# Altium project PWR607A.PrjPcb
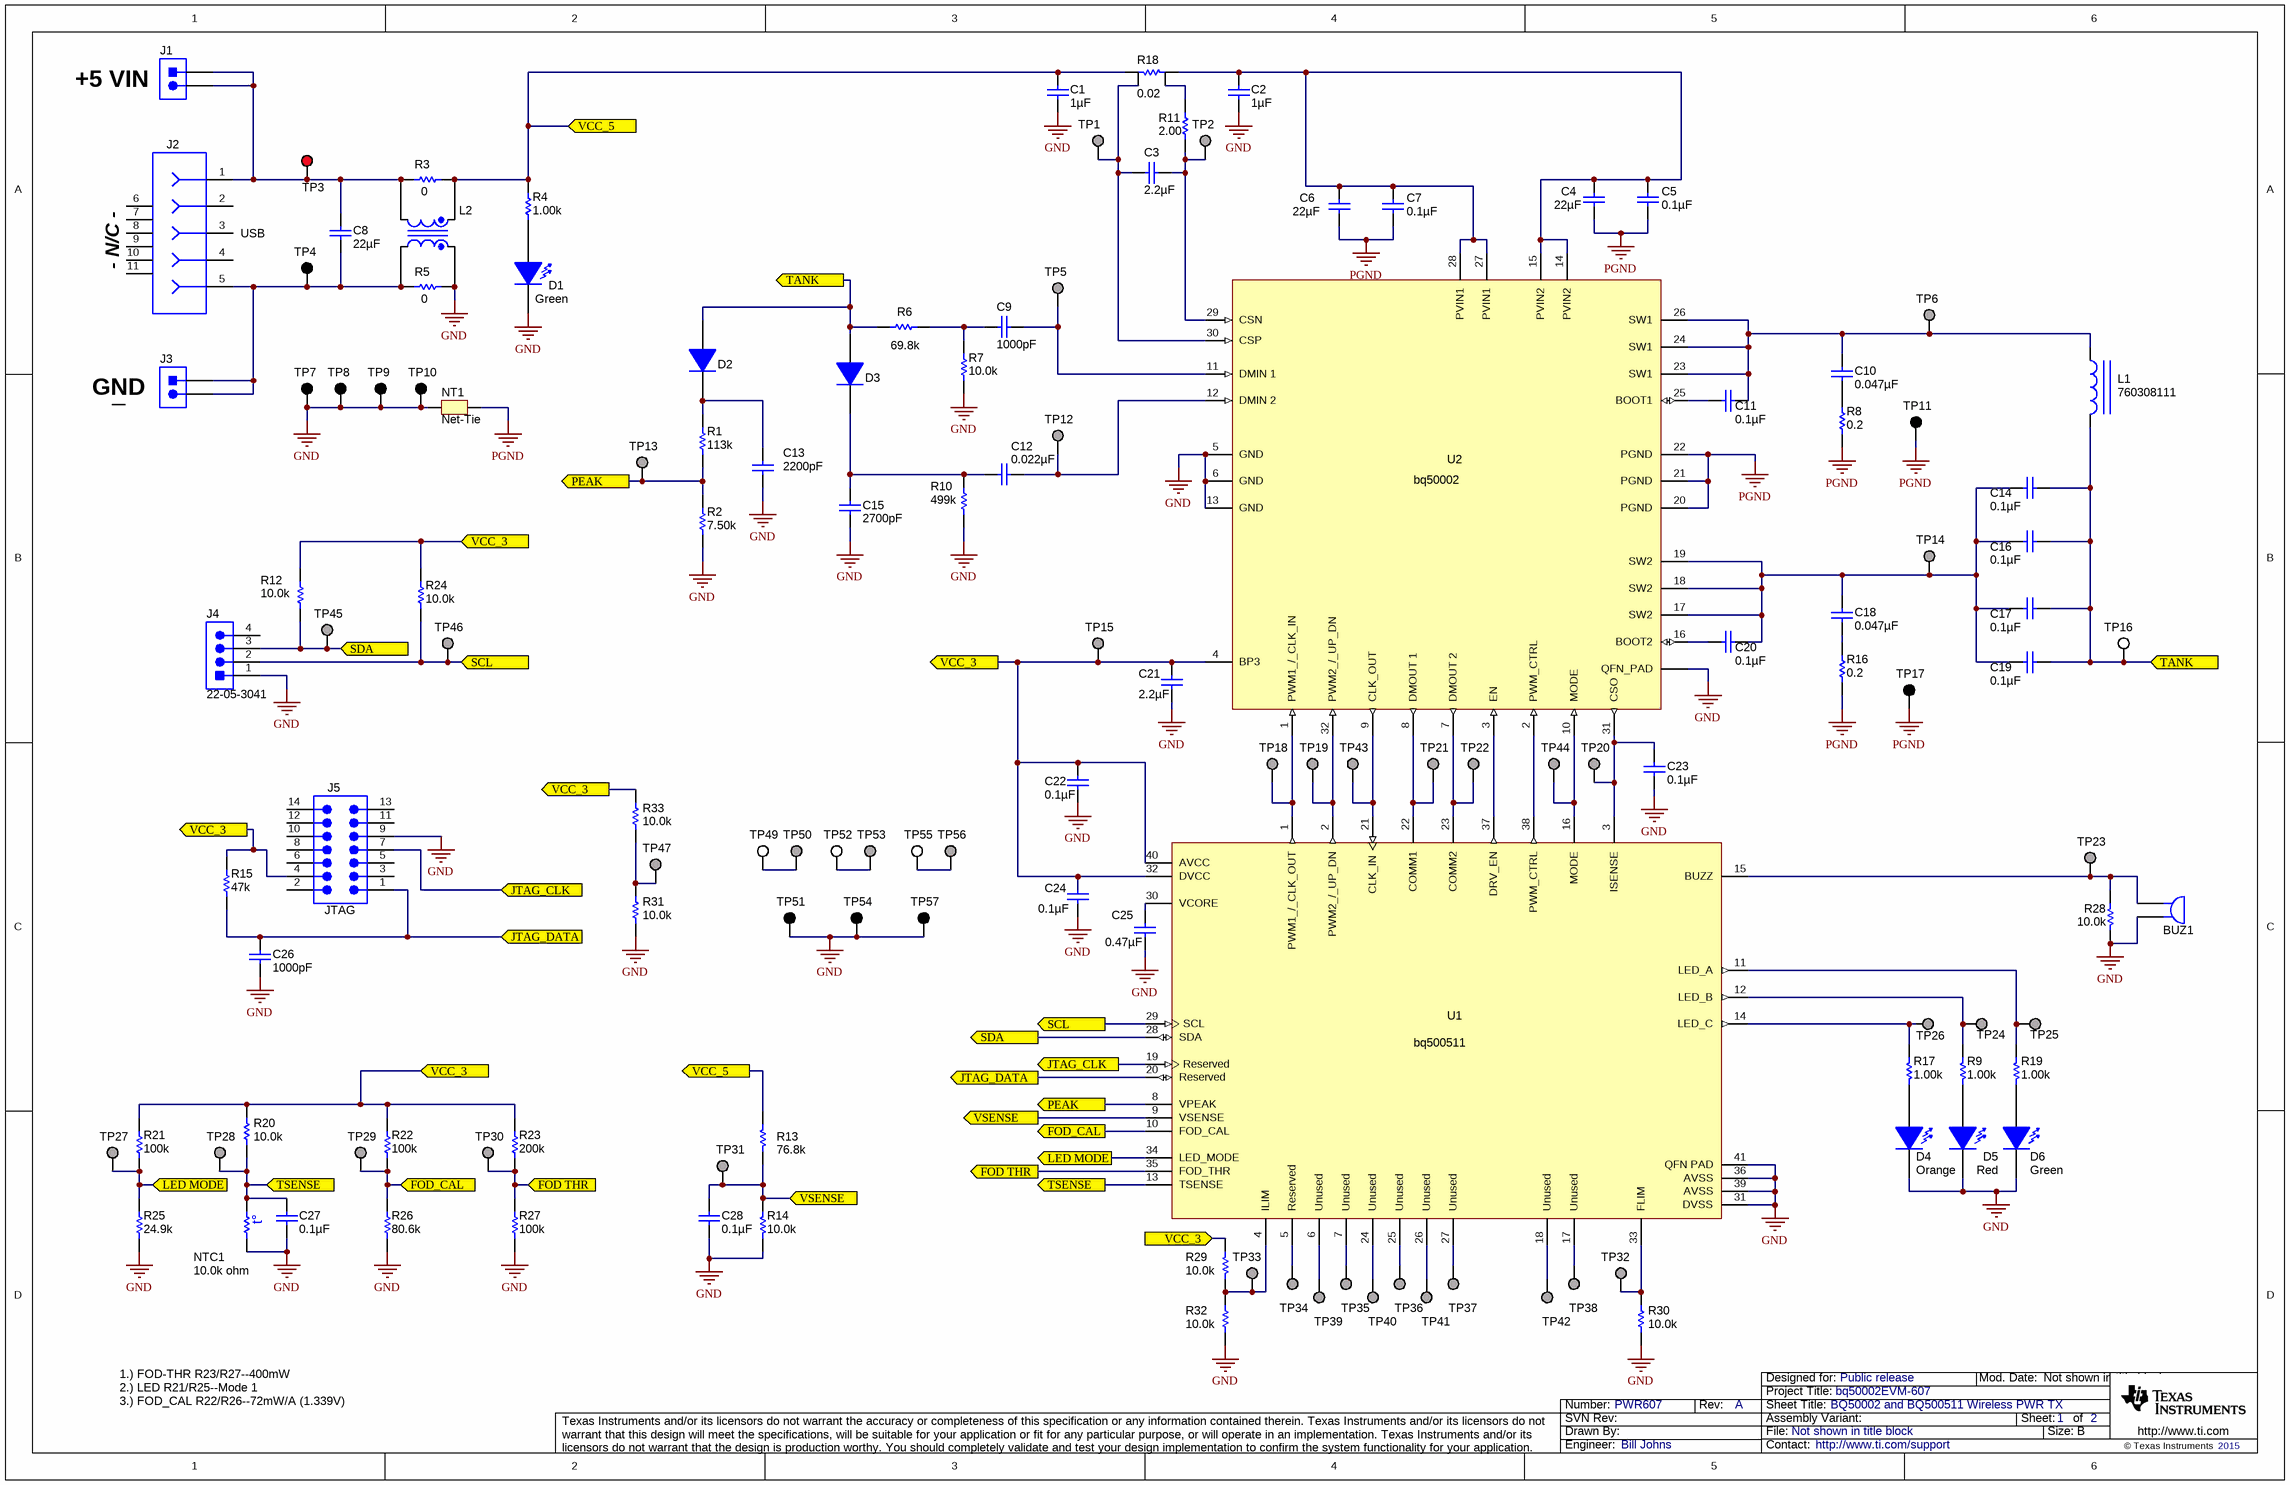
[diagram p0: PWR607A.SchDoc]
CopyrightYear: 2015; PCB_Layout: Krypton Solutions/RS; PCB_Rev: A; PRJ_Customer: Public release; PRJ_Engineer: Bill Johns; PRJ_Number: PWR607; PRJ_Title: bq50002EVM-607; SCH_Rev: A; TechSupport: http://www.ti.com/support
2 sheets, 170 parts. Net scope: flat (ports and power ports of the same name join across sheets).
Board file: PWR607A.PcbDoc
Sheets:
  PWR607A.SchDoc
  PWR607A_Hardware.SchDoc

## Sheet PWR607A.SchDoc: BQ50002 and BQ500511 Wireless PWR TX
size 431 x 279 mm; Date: Not shown in title block; ApprovedBy: Not shown in title block; CheckedBy: Not shown in title block; Author: Not shown in title block; CompanyName: Not shown in title block; Engineer: Not shown in title block; Organization: Not shown in title block; Address1: Not shown in title block; Address2: Not shown in title block; Address3: Not shown in title block; Address4: Not shown in title block; DocumentNumber: 1; Revision: Use project parameter SCH_Rev; SheetNumber: 1; SheetTotal: 2; PageSetup: Record=PageOptions¦CenterHorizontal=True¦CenterVertical=True¦PrintScale=0.64¦XCorrection=1.00¦YCorrection=1.00¦PrintKind=0¦BorderSize=5000000¦LeftOffset=0¦BottomOffset=0¦Orientation=2¦PaperLength=1000¦PaperWidth=1000¦Scale=100¦PaperSource=15¦PrintQuality=600¦MediaType=1¦DitherType=10¦PrintScaleMode=1¦PaperKind=Letter

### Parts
BUZ1  PS1240P02CT3  [TDK_PS1240P02C]  (value not drawn)
C1  ValueDisplayed: 1µF  [0603_HV]  (hidden comment: GRM188R71E105KA12D)
C2  ValueDisplayed: 1µF  [0603_HV]  (hidden comment: GRM188R71E105KA12D)
C3  ValueDisplayed: 2.2µF  [0603_HV]  (hidden comment: GRM188R71A225KE15D)
C4  ValueDisplayed: 22µF  [0805_HV]  (hidden comment: GRM21BR61E226ME44)
C5  ValueDisplayed: 0.1µF  [0603_HV]  (hidden comment: C1608X7R1E104K)
C6  ValueDisplayed: 22µF  [0805_HV]  (hidden comment: GRM21BR61E226ME44)
C7  ValueDisplayed: 0.1µF  [0603_HV]  (hidden comment: C1608X7R1E104K)
C8  ValueDisplayed: 22µF  [1210]  (hidden comment: GRM32ER71E226KE15L)
C9  ValueDisplayed: 1000pF  [0603_HV]  (hidden comment: C1608C0G1H102J)
C10  ValueDisplayed: 0.047µF  [0603_HV]  (hidden comment: C1608X7R1H473K)
C11  ValueDisplayed: 0.1µF  [0603_HV]  (hidden comment: C1608X7R1E104K)
C12  ValueDisplayed: 0.022µF  [0603]  (hidden comment: C1608X7R1H223K)
C13  ValueDisplayed: 2200pF  [0603_HV]  (hidden comment: GRM188R71H222KA01D)
C14  ValueDisplayed: 0.1µF  [1206]  (hidden comment: C3216C0G1E104J)
C15  ValueDisplayed: 2700pF  [0603_HV]  (hidden comment: C1608C0G1H272J)
C16  ValueDisplayed: 0.1µF  [1206]  (hidden comment: C3216C0G1E104J)
C17  ValueDisplayed: 0.1µF  [1206]  (hidden comment: C3216C0G1E104J)
C18  ValueDisplayed: 0.047µF  [0603_HV]  (hidden comment: C1608X7R1H473K)
C19  ValueDisplayed: 0.1µF  [1206]  (hidden comment: C3216C0G1E104J)
C20  ValueDisplayed: 0.1µF  [0603_HV]  (hidden comment: C1608X7R1E104K)
C21  ValueDisplayed: 2.2µF  [0603]  (hidden comment: GRM188R61C225KE15D)
C22  ValueDisplayed: 0.1µF  [0603_HV]  (hidden comment: C1608X7R1E104K)
C23  ValueDisplayed: 0.1µF  [0603_HV]  (hidden comment: C1608X7R1E104K)
C24  ValueDisplayed: 0.1µF  [0603_HV]  (hidden comment: C1608X7R1E104K)
C25  ValueDisplayed: 0.47µF  [0603]  (hidden comment: GRM188R71A474KA61D)
C26  ValueDisplayed: 1000pF  [0603_HV]  (hidden comment: C1608C0G1H102J)
C27  ValueDisplayed: 0.1µF  [0603_HV]  (hidden comment: C1608X7R1E104K)
C28  ValueDisplayed: 0.1µF  [0603_HV]  (hidden comment: C1608X7R1E104K)
D1  value Green  [LED_LTST-C190_G]  (hidden comment: LTST-C190KGKT)
D2  MMDL914-TP  [sod-323]  (value not drawn)
D3  MMDL914-TP  [sod-323]  (value not drawn)
D4  value Orange  [LED_LTST-C190]  (hidden comment: LTST-C190KFKT)
D5  value Red  [LED_LTST-C190_Red]  (hidden comment: LTST-C190CKT)
D6  value Green  [LED_LTST-C190_G]  (hidden comment: LTST-C190KGKT)
J1  PEC02SAAN  [CONN_PEC02SAAN]  (value not drawn)
J2  105017-0001  [CONN_105017-0001]  (value not drawn)
J3  PEC02SAAN  [CONN_PEC02SAAN]  (value not drawn)
J4  22-05-3041  [CONN_22-05-3041]
J5  SBH11-PBPC-D07-ST-BK  [CONN_SBH11-PBPC-D07-ST-BK]  (value not drawn)
L1  760308111  [WE-WPCC_5353_Qi_A11]
L2  DLW5BTM102TQ2K  [DLW5BT_TQ2]  (value not drawn)
NT1  Net-Tie  [Net-Tie_20milWide_60milLong]  (net tie, no BOM)
NTC1  value 10.0k ohm  [0603]  (hidden comment: NTCG163JF103F)
R1  ValueDisplayed: 113k  [0603]  (hidden comment: RG1608P-1133-B-T5)
R2  ValueDisplayed: 7.50k  [0603]  (hidden comment: RT0603BRD077K5L)
R3  value 0  [1206L]  (hidden comment: CRCW12060000Z0EA)
R4  ValueDisplayed: 1.00k  [0603_HV]  (hidden comment: CRCW06031K00FKEA)
R5  value 0  [1206L]  (hidden comment: CRCW12060000Z0EA)
R6  value 69.8k  [0603_HV]  (hidden comment: RC0603FR-0769K8L)
R7  value 10.0k  [0603_HV]  (hidden comment: RC0603FR-0710KL)
R8  value 0.2  [0805_HV]  (hidden comment: ERJ-S6SJR20V)
R9  ValueDisplayed: 1.00k  [0603_HV]  (hidden comment: CRCW06031K00FKEA)
R10  value 499k  [0603_HV]  (hidden comment: RC0603FR-07499KL)
R11  ValueDisplayed: 2.00  [0603_HV]  (hidden comment: CRCW06032R00FKEA)
R12  value 10.0k  [0603_HV]  (hidden comment: RC0603FR-0710KL)
R13  ValueDisplayed: 76.8k  [0603_HV]  (hidden comment: RG1608P-7682-B-T5)
R14  ValueDisplayed: 10.0k  [0603_HV]  (hidden comment: RT0603BRD0710KL)
R15  value 47k  [0603]  (hidden comment: RC0603JR-0747KL)
R16  value 0.2  [0805_HV]  (hidden comment: ERJ-S6SJR20V)
R17  ValueDisplayed: 1.00k  [0603_HV]  (hidden comment: CRCW06031K00FKEA)
R18  ValueDisplayed: 0.02  [LVK12]  (hidden comment: LVK12R020DER)
R19  ValueDisplayed: 1.00k  [0603_HV]  (hidden comment: CRCW06031K00FKEA)
R20  value 10.0k  [0603_HV]  (hidden comment: RC0603FR-0710KL)
R21  ValueDisplayed: 100k  [0603]  (hidden comment: RC0603FR-07100KL)
R22  ValueDisplayed: 100k  [0603]  (hidden comment: RC0603FR-07100KL)
R23  ValueDisplayed: 200k  [0603]  (hidden comment: RC0603FR-07200KL)
R24  value 10.0k  [0603_HV]  (hidden comment: RC0603FR-0710KL)
R25  ValueDisplayed: 24.9k  [0603]  (hidden comment: RC0603FR-0724K9L)
R26  ValueDisplayed: 80.6k  [0603]  (hidden comment: RC0603FR-0780K6L)
R27  ValueDisplayed: 100k  [0603]  (hidden comment: RC0603FR-07100KL)
R28  value 10.0k  [0603_HV]  (hidden comment: RC0603FR-0710KL)
R29  value 10.0k  [0603_HV]  (hidden comment: RC0603FR-0710KL)
R30  value 10.0k  [0603_HV]  (hidden comment: RC0603FR-0710KL)
R31  value 10.0k  [0603_HV]  (hidden comment: RC0603FR-0710KL)
R32  value 10.0k  [0603_HV]  (hidden comment: RC0603FR-0710KL)
R33  value 10.0k  [0603_HV]  (hidden comment: RC0603FR-0710KL)
TP1  Pogo Pad  [PogoPad]  (value not drawn)  (no BOM)
TP2  Pogo Pad  [PogoPad]  (value not drawn)  (no BOM)
TP3  5005  [Keystone5005]  (value not drawn)
TP4  5011  [Keystone5011]  (value not drawn)
TP5  (no value)  [TESTPOINT]  (no BOM)
TP6  (no value)  [TESTPOINT]  (no BOM)
TP7  5011  [Keystone5011]  (value not drawn)
TP8  5011  [Keystone5011]  (value not drawn)
TP9  5011  [Keystone5011]  (value not drawn)
TP10  5011  [Keystone5011]  (value not drawn)
TP11  5011  [Keystone5011]  (value not drawn)
TP12  (no value)  [TESTPOINT]  (no BOM)
TP13  Pogo Pad  [PogoPad]  (value not drawn)  (no BOM)
TP14  (no value)  [TESTPOINT]  (no BOM)
TP15  Pogo Pad  [PogoPad]  (value not drawn)  (no BOM)
TP16  5007  [Keystone5007]  (value not drawn)
TP17  5011  [Keystone5011]  (value not drawn)
TP18  Pogo Pad  [PogoPad]  (value not drawn)  (no BOM)
TP19  Pogo Pad  [PogoPad]  (value not drawn)  (no BOM)
TP20  Pogo Pad  [PogoPad]  (value not drawn)  (no BOM)
TP21  (no value)  [TESTPOINT]  (no BOM)
TP22  (no value)  [TESTPOINT]  (no BOM)
TP23  Pogo Pad  [PogoPad]  (value not drawn)  (no BOM)
TP24  Pogo Pad  [PogoPad]  (value not drawn)  (no BOM)
TP25  Pogo Pad  [PogoPad]  (value not drawn)  (no BOM)
TP26  Pogo Pad  [PogoPad]  (value not drawn)  (no BOM)
TP27  Pogo Pad  [PogoPad]  (value not drawn)  (no BOM)
TP28  Pogo Pad  [PogoPad]  (value not drawn)  (no BOM)
TP29  Pogo Pad  [PogoPad]  (value not drawn)  (no BOM)
TP30  Pogo Pad  [PogoPad]  (value not drawn)  (no BOM)
TP31  (no value)  [TESTPOINT]  (no BOM)
TP32  Pogo Pad  [PogoPad]  (value not drawn)  (no BOM)
TP33  Pogo Pad  [PogoPad]  (value not drawn)  (no BOM)
TP34  Pogo Pad  [PogoPad]  (value not drawn)  (no BOM)
TP35  Pogo Pad  [PogoPad]  (value not drawn)  (no BOM)
TP36  Pogo Pad  [PogoPad]  (value not drawn)  (no BOM)
TP37  Pogo Pad  [PogoPad]  (value not drawn)  (no BOM)
TP38  Pogo Pad  [PogoPad]  (value not drawn)  (no BOM)
TP39  Pogo Pad  [PogoPad]  (value not drawn)  (no BOM)
TP40  Pogo Pad  [PogoPad]  (value not drawn)  (no BOM)
TP41  Pogo Pad  [PogoPad]  (value not drawn)  (no BOM)
TP42  Pogo Pad  [PogoPad]  (value not drawn)  (no BOM)
TP43  Pogo Pad  [PogoPad]  (value not drawn)  (no BOM)
TP44  Pogo Pad  [PogoPad]  (value not drawn)  (no BOM)
TP45  Pogo Pad  [PogoPad]  (value not drawn)  (no BOM)
TP46  Pogo Pad  [PogoPad]  (value not drawn)  (no BOM)
TP47  Pogo Pad  [PogoPad]  (value not drawn)  (no BOM)
TP49  5002  [Keystone5002]  (value not drawn)
TP50  Pogo Pad  [PogoPad]  (value not drawn)  (no BOM)
TP51  5011  [Keystone5011]  (value not drawn)
TP52  5002  [Keystone5002]  (value not drawn)
TP53  Pogo Pad  [PogoPad]  (value not drawn)  (no BOM)
TP54  5011  [Keystone5011]  (value not drawn)
TP55  5002  [Keystone5002]  (value not drawn)
TP56  Pogo Pad  [PogoPad]  (value not drawn)  (no BOM)
TP57  5011  [Keystone5011]  (value not drawn)
U1  bq500511  [RHA0040A]
U2  bq50002  [RHB0032E]

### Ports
FOD THR, FOD_CAL, JTAG_CLK, JTAG_DATA, LED MODE, PEAK, SCL, SDA, TANK, TSENSE, VCC_3, VCC_5, VSENSE

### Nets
GND: BUZ1.2 C1.1 C2.1 C13.2 C15.2 C21.2 C22.2 C23.1 C24.1 C25.1 C26.2 C27.1 C28.2 D1.2(K) D4.2(K) D5.2(K) D6.2(K) J4.1 J5.9 L2.4 NT1.1 NTC1.1 R2.1 R5.2 R7.1 R10.1 R14.1 R25.1 R26.1 R27.1 R28.1 R30.2 R31.2 R32.1 TP7.1 TP8.1 TP9.1 TP10.1 TP51.1 TP54.1 TP57.1 U1.31(DVSS) U1.36(AVSS) U1.39(AVSS) U1.41(QFN_PAD) U2.5(GND) U2.6(GND) U2.13(GND) U2.33(QFN_PAD)
PGND: C4.2 C5.1 C6.2 C7.1 NT1.2 R8.1 R16.1 TP11.1 TP17.1 U2.20(PGND) U2.21(PGND) U2.22(PGND)
FOD THR: R23.1 R27.2 TP30.1 U1.35(FOD_THR) ; port FOD THR
FOD_CAL: R22.1 R26.2 TP29.1 U1.10(FOD_CAL) ; port FOD_CAL
JTAG_CLK: J5.7 U1.19(Reserved) ; port JTAG_CLK
JTAG_DATA: C26.1 J5.1 R15.1 U1.20(Reserved) ; port JTAG_DATA
LED MODE: R21.1 R25.2 TP27.1 U1.34(LED_MODE) ; port LED MODE
PEAK: R1.1 R2.2 TP13.1 U1.8(VPEAK) ; port PEAK
SCL: J4.2 R24.1 TP46.1 U1.29(SCL) ; port SCL
SDA: J4.3 R12.1 TP45.1 U1.28(SDA) ; port SDA
TANK: C14.1 C16.1 C17.1 C19.1 D2.2(A) D3.2(A) L1.2 R6.2 TP16.1 ; port TANK
TSENSE: C27.2 NTC1.2 R20.2 TP28.1 U1.13(TSENSE) ; port TSENSE
VCC_3: C21.1 C22.1 C24.2 J5.4 R12.2 R15.2 R20.1 R21.2 R22.2 R23.2 R24.2 R29.1 R33.1 TP15.1 U1.32(DVCC) U1.40(AVCC) U2.4(BP3) ; port VCC_3
VCC_5: C1.2 L2.1 R3.2 R4.2 R13.2 R18.1 ; port VCC_5
VSENSE: C28.1 R13.1 R14.2 TP31.1 U1.9(VSENSE) ; port VSENSE
NetBUZ1_1: BUZ1.1 R28.2 TP23.1 U1.15(BUZZ)
NetC2_2: C2.2 C4.1 C5.2 C6.1 C7.2 R18.2 U2.14(PVIN2) U2.15(PVIN2) U2.27(PVIN1) U2.28(PVIN1)
NetC3_1: C3.1 R18.3 TP1.1 U2.30(CSP)
NetC3_2: C3.2 R11.1 TP2.1 U2.29(CSN)
NetC8_1: C8.1 J1.1 J1.2 J2.1 L2.2 R3.1 TP3.1
NetC8_2: C8.2 J2.5 J3.1 J3.2 L2.3 R5.1 TP4.1
NetC9_1: C9.1 R6.1 R7.2
NetC9_2: C9.2 TP5.1 U2.11(DMIN_1)
NetC10_1: C10.1 C11.2 L1.1 TP6.1 U2.23(SW1) U2.24(SW1) U2.26(SW1)
NetC10_2: C10.2 R8.2
NetC11_1: C11.1 U2.25(BOOT1)
NetC12_1: C12.1 C15.1 D3.1(K) R10.2
NetC12_2: C12.2 TP12.1 U2.12(DMIN_2)
NetC13_1: C13.1 D2.1(K) R1.2
NetC14_2: C14.2 C16.2 C17.2 C18.1 C19.2 C20.1 TP14.1 U2.17(SW2) U2.18(SW2) U2.19(SW2)
NetC18_2: C18.2 R16.2
NetC20_2: C20.2 U2.16(BOOT2)
NetC23_2: C23.2 TP20.1 U1.3(ISENSE) U2.31(CSO)
NetC25_2: C25.2 U1.30(VCORE)
NetD1_1: D1.1(A) R4.1
NetD4_1: D4.1(A) R17.1
NetD5_1: D5.1(A) R9.1
NetD6_1: D6.1(A) R19.1
NetR9_2: R9.2 TP24.1 U1.12(LED_B)
NetR11_2: R11.2 R18.4
NetR17_2: R17.2 TP26.1 U1.14(LED_C)
NetR19_2: R19.2 TP25.1 U1.11(LED_A)
NetR29_2: R29.2 R32.2 TP33.1 U1.4(ILIM)
NetR30_1: R30.1 TP32.1 U1.33(FLIM)
NetR31_1: R31.1 R33.2 TP47.1
NetTP18_1: TP18.1 U1.1(PWM1_/_CLK_OUT) U2.1(PWM1_/_CLK_IN)
NetTP19_1: TP19.1 U1.2(PWM2_/_UP_DN) U2.32(PWM2_/_UP_DN)
NetTP21_1: TP21.1 U1.22(COMM1) U2.8(DMOUT_1)
NetTP22_1: TP22.1 U1.23(COMM2) U2.7(DMOUT_2)
NetTP34_1: TP34.1 U1.5(Reserved)
NetTP35_1: TP35.1 U1.7(Unused)
NetTP36_1: TP36.1 U1.25(Unused)
NetTP37_1: TP37.1 U1.27(Unused)
NetTP38_1: TP38.1 U1.17(Unused)
NetTP39_1: TP39.1 U1.6(Unused)
NetTP40_1: TP40.1 U1.24(Unused)
NetTP41_1: TP41.1 U1.26(Unused)
NetTP42_1: TP42.1 U1.18(Unused)
NetTP43_1: TP43.1 U1.21(CLK_IN) U2.9(CLK_OUT)
NetTP44_1: TP44.1 U1.16(MODE) U2.10(MODE)
NetTP49_1: TP49.1 TP50.1
NetTP52_1: TP52.1 TP53.1
NetTP55_1: TP55.1 TP56.1
NetU1_37: U1.37(DRV_EN) U2.3(EN)
NetU1_38: U1.38(PWM_CTRL) U2.2(PWM_CTRL)

Not connected (* = marked no-connect by the designer): J2 2 3 4 6 7 8 9 10 11; J4 4; J5 2 3 5 6 8 10 11 12 13 14

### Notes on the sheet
- (near J1) +5 VIN
- USB
- (near J2) - N/C -
- (near J3) GND
- _
- (near J5) JTAG
- 1.) FOD-THR R23/R27--400mW
  2.) LED R21/R25--Mode 1
  3.) FOD_CAL R22/R26--72mW/A (1.339V)

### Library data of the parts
BUZ1 = PS1240P02CT3: Buzzer, Piezo, 4kHz, 12.2mm, TH; Manufacturer: TDK; SymbolCreator: a0411947
C1 C2 = GRM188R71E105KA12D: CAP, CERM, 1 µF, 25 V, +/- 10%, X7R, 0603; Manufacturer: MuRata; Polarized: N; CompType: Capacitor; Value: 1uF; U/M: EA; Cap_F: 0.000001; Tolerance_%: 10; Value1: Unknown; VDC_V: 25; Value2: 25V; TaMin_C: -55; TaMax_C: 125; Cap_Case: 0603
C3 = GRM188R71A225KE15D: CAP, CERM, 2.2 µF, 10 V, +/- 10%, X7R, 0603; Manufacturer: MuRata; Polarized: N; CompType: Capacitor; Value: 2.2uF; U/M: EA; Cap_F: 0.0000022; Tolerance_%: 10; ESR_ohm: 0.009; Value1: 0.009 ohm; Value2: 10V; TaMin_C: -55; TaMax_C: 125; Cap_Case: 0603
C4 C6 = GRM21BR61E226ME44: CAP, CERM, 22uF, 25V, +/-20%, X5R, 0805; Manufacturer: MuRata; Polarized: N; CompType: Capacitor; U/M: EA; Cap_F: 0.000022; Tolerance_%: 20; Value1: Unknown; VDC_V: 25; TaMin_C: -55; TaMax_C: 85; Cap_Case: 0805
C5 C7 C11 C20 C22-C24 C27 C28 = C1608X7R1E104K: CAP, CERM, 0.1uF, 25V, +/-10%, X7R, 0603; Manufacturer: TDK; Polarized: N; CompType: Capacitor; U/M: EA; Cap_F: 0.0000001; Tolerance_%: 10; ESR_Ohm: 0.017; Value1: 0.017 ohm; VDC_V: 25; TaMin_C: -55; TaMax_C: 125; Cap_Case: 0603
C8 = GRM32ER71E226KE15L: CAP, CERM, 22uF, 25V, +/-10%, X7R, 1210; Manufacturer: MuRata; Polarized: N; CompType: Capacitor; U/M: EA; Cap_F: 0.000022; Tolerance_%: 10; Value1: Unknown; VDC_V: 25; TaMin_C: -55; TaMax_C: 125
C9 C26 = C1608C0G1H102J: CAP, CERM, 1000pF, 50V, +/-5%, C0G/NP0, 0603; Manufacturer: TDK; Polarized: N; CompType: Capacitor; U/M: EA; Cap_F: 0.000000001; Tolerance_%: 5; ESR_Ohm: 0.0563; Value1: 0.0563 ohm; VDC_V: 50; TaMin_C: -55; TaMax_C: 125; Cap_Case: 0603
C10 C18 = C1608X7R1H473K: CAP, CERM, 0.047uF, 50V, +/-10%, X7R, 0603; Manufacturer: TDK; Polarized: N; CompType: Capacitor; U/M: EA; Cap_F: 0.000000047; Tolerance_%: 10; ESR_Ohm: 0.0234; Value1: 0.0234 ohm; VDC_V: 50; TaMin_C: -55; TaMax_C: 125; Cap_Case: 0603
C12 = C1608X7R1H223K: CAP, CERM, 0.022 µF, 50 V, +/- 10%, X7R, 0603; Manufacturer: TDK; Polarized: N; CompType: Capacitor; Value: 0.022uF; U/M: EA; Cap_F: 0.000000022; Tolerance_%: 10; ESR_ohm: 0.0383; Value1: 0.0383 ohm; VDC_V: 50; Value2: 50V; TaMin_C: -55; TaMax_C: 125
C13 = GRM188R71H222KA01D: CAP, CERM, 2200 pF, 50 V, +/- 10%, X7R, 0603; Manufacturer: MuRata; Polarized: N; CompType: Capacitor; Value: 2200pF; U/M: EA; Cap_F: 0.0000000022; Tolerance_%: 10; Value1: Unknown; VDC_V: 50; Value2: 50V; TaMin_C: -55; TaMax_C: 125; Cap_Case: 0603
C14 C16 C17 C19 = C3216C0G1E104J: CAP, CERM, 0.1 µF, 25 V, +/- 5%, C0G/NP0, 1206; Manufacturer: TDK; Polarized: N; CompType: Capacitor; Value: 0.1uF; U/M: EA; Cap_F: 0.0000001; Tolerance_%: 5; Value1: Unknown; VDC_V: 25; Value2: 25V; TaMin_C: -55; TaMax_C: 125
C15 = C1608C0G1H272J: CAP, CERM, 2700pF, 50V, +/-5%, C0G/NP0, 0603; Manufacturer: TDK; Polarized: N; CompType: Capacitor; U/M: EA; Cap_F: 0.0000000027; Tolerance_%: 5; Value1: Unknown; VDC_V: 50; TaMin_C: -55; TaMax_C: 125; Cap_Case: 0603
C21 = GRM188R61C225KE15D: CAP, CERM, 2.2uF, 16V, +/-10%, X5R, 0603; Manufacturer: MuRata; Polarized: N; CompType: Capacitor; U/M: EA; Cap_F: 0.0000022; Tolerance_%: 10; Value1: Unknown; VDC_V: 16; TaMin_C: -55; TaMax_C: 85
C25 = GRM188R71A474KA61D: CAP, CERM, 0.47uF, 10V, +/-10%, X7R, 0603; Manufacturer: MuRata; Polarized: N; CompType: Capacitor; U/M: EA; Cap_F: 0.00000047; Tolerance_%: 10; Value1: Unknown; TaMin_C: -55; TaMax_C: 125
D1 D6 = LTST-C190KGKT: LED, Green, SMD; Manufacturer: Lite-On; Type: AlInGaP; Vf_V: 2; Value2: 2V; Io_A: 0.03; Tjmax_C: 85; Value1: W; U/M: EA
D2 D3 = MMDL914-TP: Diode, Switching, 100V, 0.2A, SOD-323; Manufacturer: Micro Commercial Components; U/M: EA; Vf_V: 1; Value2: 1V; Io_A: 0.2; Vr_V: 100; TJmax_C: 150; RJC_CperW: 635
D4 = LTST-C190KFKT: LED, Orange, SMD; Manufacturer: Lite-On; Type: AlInGaP; Vf_V: 2; Value2: 2V; Io_A: 0.02; Power_TotalModule: 0.075; Value1: 0.075W; U/M: EA
D5 = LTST-C190CKT: LED, Red, SMD; Manufacturer: Lite-On; Vf_V: 2; Value2: 2V; Io_A: 0.02; Tjmax_C: 85; Power_TotalModule: 0.0625; Value1: 0.0625W; U/M: EA
J1 J3 = PEC02SAAN: Header, 100mil, 2x1, Tin, TH; Manufacturer: Sullins Connector Solutions; SymbolCreator: a0412235; U/M: EA
J2 = 105017-0001: Receptacle, Micro-USB-B, Right Angle, SMD; Manufacturer: Molex; SymbolCreator: a0412235; CompType: Connector; U/M: EA
J4 = 22-05-3041: Header (friction lock), 100mil, 4x1, R/A, TH; Manufacturer: Molex; SymbolCreator: a0412235; U/M: EA
J5 = SBH11-PBPC-D07-ST-BK: Header (shrouded), 100 mil, 7x2, Gold plated, TH; Manufacturer: Sullins Connector Solutions; SymbolCreator: a0412235; CompType: Connector; U/M: EA
L1 = 760308111: Inductor, 6.3 µH, 13 A, 0.017 ohm, TH; Manufacturer: Wurth Elektronik; Value: 6.3uH; Ind_H: 6.3E-6; ValueDisplayed: 6.3µH; Imax_A: 13; Irms: 13A @ 40C rise; Isat: 16A @ % inductance drop; DCR_ohm: 0.017; Value2: 13A
L2 = DLW5BTM102TQ2K: Coupled inductor, 2.5 A, 0.034 ohm, SMD; Manufacturer: MuRata; SymbolCreator: a0412235; DCR_ohm: 0.034; Isat: 2.5
NT1 = Net-Tie: Single point connection between nets.; SymbolCreator: codlsc
NTC1 = NTCG163JF103F: Thermistor NTC, 10.0k ohm, 1%, 0603; Manufacturer: TDK; Tolerance_%: 1; TaMin_C: -40; TaMax_C: 125; U/M: EA
R1 = RG1608P-1133-B-T5: RES, 113 k, 0.1%, 0.1 W, 0603; Manufacturer: Susumu Co Ltd; CompType: Resistor; Value: 113k; Res_ohm: 113000; Tolerance_%: 0.1; Value2: 0.1W; VDC_V: 75; TempCo: 25 ppm/C; EIA_Code: E192; U/M: EA
R2 = RT0603BRD077K5L: RES, 7.50 k, 0.1%, 0.1 W, 0603; Manufacturer: Yageo America; CompType: Resistor; Value: 7.50k; Res_ohm: 7500; Value_Code: 7k50; Tolerance_%: 0.1; Value2: 0.1W; VDC_V: 75; TempCo: 25 ppm/C; EIA_Code: E192; U/M: EA; AEC Category: Q200
R3 R5 = CRCW12060000Z0EA: RES, 0 ohm, 5%, 0.25W, 1206; Manufacturer: Vishay-Dale; CompType: Resistor; Value_Code: 0000; Tolerance_%: 5; Power_W: 0.25; VDC_V: 200; TempCo: 200 ppm/C; EIA_Code: E24; U/M: EA
R4 R19 = CRCW06031K00FKEA: RES, 1.00 k, 1%, 0.1 W, 0603; Manufacturer: Vishay-Dale; CompType: Resistor; Value: 1.00k; Res_ohm: 1000; Value_Code: 1k00; Tolerance_%: 1; Power_W: 0.1; Value2: 0.1W; VDC_V: 75; TempCo: 100 ppm/C; EIA_Code: E96; U/M: EA
R6 = RC0603FR-0769K8L: RES, 69.8k ohm, 1%, 0.1W, 0603; Manufacturer: Yageo America; CompType: Resistor; Res_ohm: 69800; Value_Code: 69k8; Tolerance_%: 1; Power_W: 0.1; VDC_V: 150; TempCo: 200 ppm/C; EIA_Code: E96; U/M: EA
R7 R12 R20 R24 R28-R33 = RC0603FR-0710KL: RES, 10.0k ohm, 1%, 0.1W, 0603; Manufacturer: Yageo America; CompType: Resistor; Res_ohm: 10000; Value_Code: 10k0; Tolerance_%: 1; Power_W: 0.1; VDC_V: 150; TempCo: 200 ppm/C; EIA_Code: E96; U/M: EA
R8 R16 = CRM0805-FX-R510ELF: RES, 0.2 ohm, 5%, 0.25W, 0805; Manufacturer: Panasonic; CompType: Resistor; Value_Code: R510; Tolerance_%: 1; Power_W: 0.25; VDC_V: 0; TempCo: 150 ppm/C; EIA_Code: E96; U/M: EA
R9 R17 = CRCW06031K00FKEA: RES, 1.00 k, 1%, 0.1 W, 0603; Manufacturer: Vishay-Dale; CompType: Resistor; Res_ohm: 1000; Value_Code: 1k00; Tolerance_%: 1; Power_W: 0.1; Value2: 0.1W; VDC_V: 75; TempCo: 100 ppm/C; EIA_Code: E96; Value: 1.00k; U/M: EA
R10 = RC0603FR-07499KL: RES, 499k ohm, 1%, 0.1W, 0603; Manufacturer: Yageo America; CompType: Resistor; Res_ohm: 499000; Tolerance_%: 1; Power_W: 0.1; VDC_V: 150; TempCo: 200 ppm/C; EIA_Code: E96; U/M: EA
R11 = CRCW06032R00FKEA: RES, 2.00, 1%, 0.1 W, 0603; Manufacturer: Vishay-Dale; CompType: Resistor; Value: 2.00; Res_ohm: 2; Value_Code: 2R00; Tolerance_%: 1; Power_W: 0.1; Value2: 0.1W; VDC_V: 75; TempCo: 100 ppm/C; EIA_Code: E96; U/M: EA
R13 = RG1608P-7682-B-T5: RES, 76.8 k, 0.1%, 0.1 W, 0603; Manufacturer: Susumu Co Ltd; CompType: Resistor; Value: 76.8k; Res_ohm: 76800; Value_Code: 76k8; Tolerance_%: 0.1; Value2: 0.1W; VDC_V: 75; TempCo: 25 ppm/C; EIA_Code: E192; U/M: EA
R14 = RT0603BRD0710KL: RES, 10.0 k, 0.1%, 0.1 W, 0603; Manufacturer: Yageo America; CompType: Resistor; Value: 10.0k; Res_ohm: 10000; Value_Code: 10k0; Tolerance_%: 0.1; Value2: 0.1W; VDC_V: 75; TempCo: 25 ppm/C; EIA_Code: E192; U/M: EA
R15 = RC0603JR-0747KL: RES, 47k ohm, 5%, 0.1W, 0603; Manufacturer: Yageo America; CompType: Resistor; Res_ohm: 47000; Value_Code: 47k0; Tolerance_%: 5; Power_W: 0.1; VDC_V: 50; TempCo: 100 ppm/C; EIA_Code: E24; U/M: EA
R18 = LVK12R020DER: RES, 0.02, 0.5%, 0.5 W, 1206 sense; Manufacturer: Ohmite; CompType: Resistor; Value: 0.02; Value_Code: R020; Tolerance_%: 0.5; Value2: 0.5W; TempCo: 50 ppm/C; U/M: EA
R21 R22 R27 = RC0603FR-07100KL: RES, 100 k, 1%, 0.1 W, 0603; Manufacturer: Yageo America; CompType: Resistor; Value: 100k; Res_ohm: 100000; Tolerance_%: 1; Power_W: 0.1; Value2: 0.1W; VDC_V: 150; TempCo: 200 ppm/C; EIA_Code: E96; U/M: EA
R23 = RC0603FR-07200KL: RES, 200 k, 1%, 0.1 W, 0603; Manufacturer: Yageo America; CompType: Resistor; Value: 200k; Res_ohm: 200000; Tolerance_%: 1; Power_W: 0.1; Value2: 0.1W; VDC_V: 150; TempCo: 200 ppm/C; EIA_Code: E96; U/M: EA
R25 = RC0603FR-0724K9L: RES, 24.9 k, 1%, 0.1 W, 0603; Manufacturer: Yageo America; CompType: Resistor; Value: 24.9k; Res_ohm: 24900; Value_Code: 24k9; Tolerance_%: 1; Power_W: 0.1; Value2: 0.1W; VDC_V: 150; TempCo: 200 ppm/C; EIA_Code: E96; U/M: EA
R26 = RC0603FR-0780K6L: RES, 80.6 k, 1%, 0.1 W, 0603; Manufacturer: Yageo America; CompType: Resistor; Value: 80.6k; Res_ohm: 80600; Value_Code: 80k6; Tolerance_%: 1; Power_W: 0.1; Value2: 0.1W; VDC_V: 150; TempCo: 200 ppm/C; EIA_Code: E96; U/M: EA
TP1 TP2 TP13 TP15 TP18-TP20 TP23-TP30 TP32-TP47 TP50 TP53 TP56 = Pogopad: Pad for Pogo Pin Connector; SymbolCreator: codlsc
TP3 = 5005: Test Point, Compact, Red, TH; Manufacturer: Keystone; CompType: Test Point Loop; U/M: EA
TP4 TP7-TP11 TP17 TP51 TP54 TP57 = 5011: Test Point, Multipurpose, Black, TH; Manufacturer: Keystone; CompType: Test Point Loop; U/M: EA
TP5 TP6 TP12 TP14 TP21 TP22 TP31 = TESTPOINT: TEST POINT.  No entry in BOM.
TP16 = 5007: Test Point, Compact, White, TH; Manufacturer: Keystone; CompType: Test Point Loop; U/M: EA
TP49 TP52 TP55 = 5002: Test Point, Miniature, White, TH; Manufacturer: Keystone; CompType: Test Point Loop; U/M: EA
U1 = BQ500511RHAR: BQ500511RHA, RHA0040A; Alternate PartNumber: BQ500511RHAT; Manufacturer: Texas Instruments; SymbolCreator: Altium; CompType: IC; U/M: EA
U2 = BQ50002RHB: 4.2V to 5.5V Input, 3A Full Bridge, 2 Channel Analog Demodulation Wireless Power TX-Driver for Wireless Charging Applications, RHB0032E; Alternate Manufacturer: None; Manufacturer: Texas Instruments; SymbolCreator: x0208325; CompType: IC; U/M: EA

## Sheet PWR607A_Hardware.SchDoc
size 431 x 279 mm; Date: Not shown in title block; ApprovedBy: Not shown in title block; CheckedBy: Not shown in title block; Author: Not shown in title block; CompanyName: Not shown in title block; DrawnBy: Illya Kovarik; Engineer: Not shown in title block; Organization: Not shown in title block; Address1: Not shown in title block; Address2: Not shown in title block; Address3: Not shown in title block; Address4: Not shown in title block; DocumentNumber: 3; Revision: Use project parameter SCH_Rev; SheetNumber: 2; SheetTotal: 2; PageSetup: Record=PageOptions¦CenterHorizontal=True¦CenterVertical=True¦PrintScale=1.00¦XCorrection=1.00¦YCorrection=1.00¦PrintKind=0¦BorderSize=5000000¦LeftOffset=0¦BottomOffset=0¦Orientation=2¦PaperLength=1000¦PaperWidth=1000¦Scale=100¦PaperSource=15¦PrintQuality=600¦MediaType=1¦DitherType=10¦PaperKind=Letter¦PrintScaleMode=1
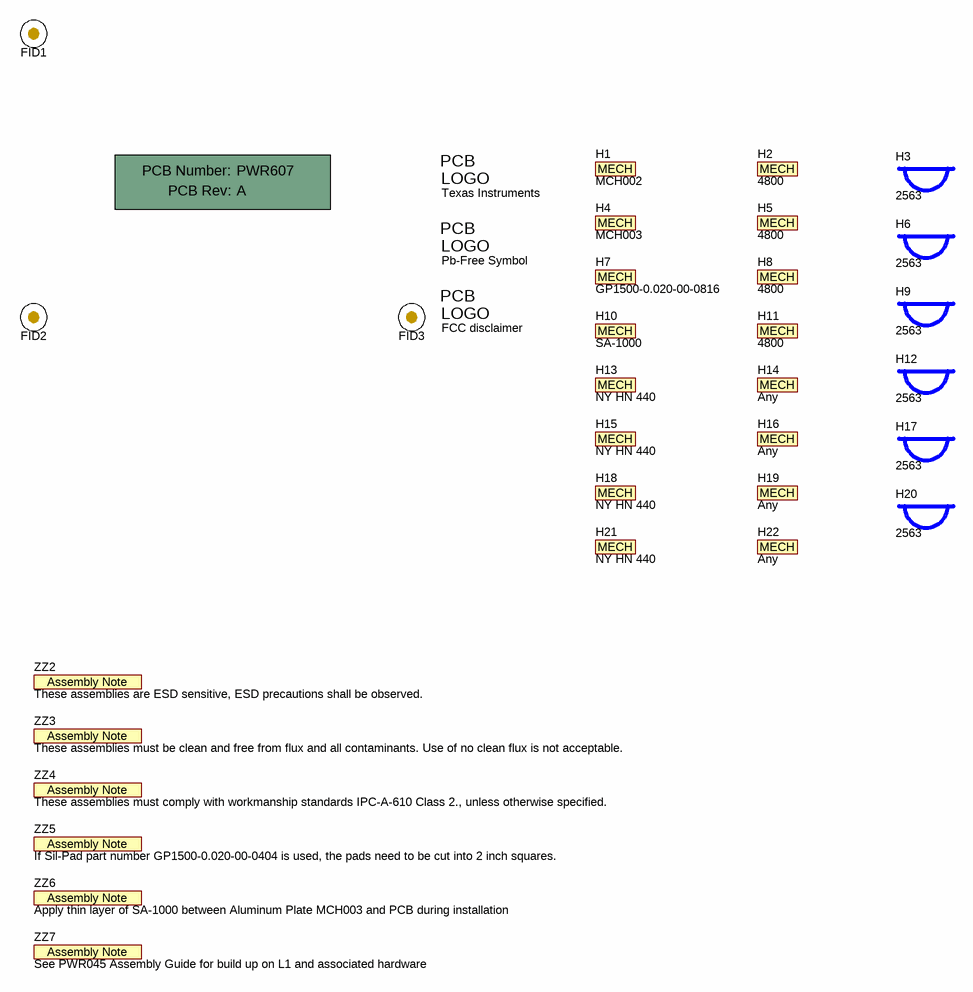
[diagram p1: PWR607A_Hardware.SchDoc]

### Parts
!PCB1  Printed Circuit Board  (value not drawn)  (mechanical)
FID1  Fiducial  [Fiducial10-20]  (value not drawn)
FID2  Fiducial  [Fiducial10-20]  (value not drawn)
FID3  Fiducial  [Fiducial10-20]  (value not drawn)
H1  MCH002  (mechanical)
H2  4800  (mechanical)
H3  2563  [Bumpon_SJ61A1]
H4  MCH003  (mechanical)
H5  4800  (mechanical)
H6  2563  [Bumpon_SJ61A1]
H7  GP1500-0.020-00-0816  (mechanical)
H8  4800  (mechanical)
H9  2563  [Bumpon_SJ61A1]
H10  SA-1000  (mechanical)
H11  4800  (mechanical)
H12  2563  [Bumpon_SJ61A1]
H13  NY HN 440  (mechanical)
H14  Any  (mechanical)
H15  NY HN 440  (mechanical)
H16  Any  (mechanical)
H17  2563  [Bumpon_SJ61A1]
H18  NY HN 440  (mechanical)
H19  Any  (mechanical)
H20  2563  [Bumpon_SJ61A1]
H21  NY HN 440  (mechanical)
H22  Any  (mechanical)
Logo1  Texas Instruments  [TI_Stacked_Overlay_Small]  (no BOM)
Logo2  Pb-Free Symbol  [Pb-Free_Overlay_Medium]  (no BOM)
Logo3  FCC disclaimer  [FCC_disclaimer_stacked]  (no BOM)
ZZ2  These assemblies are ESD sensitive, ESD precautions shall be observed.  [AssemblyNote]  (no BOM)
ZZ3  These assemblies must be clean and free from flux and all contaminants. Use of no clean flux is not acceptable.  [AssemblyNote]  (no BOM)
ZZ4  These assemblies must comply with workmanship standards IPC-A-610 Class 2., unless otherwise specified.  [AssemblyNote]  (no BOM)
ZZ5  If Sil-Pad part number GP1500-0.020-00-0404 is used, the pads need to be cut into 2 inch squares.  [AssemblyNote]  (no BOM)
ZZ6  Apply thin layer of SA-1000 between Aluminum Plate MCH003 and PCB during installation  [AssemblyNote]  (no BOM)
ZZ7  See PWR045 Assembly Guide for build up on L1 and associated hardware  [AssemblyNote]  (no BOM)

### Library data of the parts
!PCB1 = PCB: Manufacturer: Any; PartNumber: PWR607; SymbolCreator: a0412235
FID1-FID3 = Fiducial: Fiducial mark.  There is nothing to buy or mount.; SymbolCreator: codlsc
H1 = MechPart: Cover, Plastic Polycarbonate, 2.75 " Square, 0.93 thick; Manufacturer: Any; SymbolCreator: codlsc; CompType: Mechanical; U/M: EA
H2 H5 H8 H11 = MechPart: Standoff, Nylon, Female to Male, 4-40 x 1/4"; Manufacturer: Keystone; SymbolCreator: codlsc; CompType: Mechanical; U/M: EA
H3 H6 H9 H12 H17 H20 = SJ61A1: Mounting Feet, 0.25" tall; Manufacturer: Voltrex; SymbolCreator: a0412235; CompType: Bumpon
H4 = MechPart: Plate, aluminum  2.0"x2.0"x0.062"; Manufacturer: Any; SymbolCreator: codlsc; CompType: Mechanical; U/M: EA
H7 = MechPart: Sil-Pad  Cut to Size 2.0" Square; Manufacturer: Bergquist; Alternate PartNumber: GP1500-0.020-00-0404; SymbolCreator: codlsc; CompType: Mechanical; U/M: EA
H10 = MechPart: Adhesive, Thermally Conductive Silicone; Manufacturer: Bergquist; SymbolCreator: codlsc; CompType: Mechanical; U/M: EA
H13 H15 H18 H21 = MechPart: Nut #4-40 Hex Nylon; Manufacturer: B&F Fastener Supply; SymbolCreator: codlsc; CompType: Mechanical; U/M: EA
H14 H16 H19 H22 = MechPart: Screw, steel zinc, flathead 4-40 machine, 0.250"; SymbolCreator: codlsc; CompType: Mechanical; U/M: EA
Logo1 = TI_Logo: Texas Instrument Corporate Signature; SymbolCreator: codlsc
Logo2 = Pb-Free: SymbolCreator: a0412235
Logo3 = FCC_disclaimer: SymbolCreator: codlsc
ZZ2-ZZ4 = AssemblyNote: SymbolCreator: codlsc
ZZ5-ZZ7 = Assembly Note: SymbolCreator: codlsc

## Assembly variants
001: not fitted C28 FID1 FID2 FID3 L2 R29 R30 R31 R32 R33 TP1 TP2 TP5 TP6 TP12 TP13 TP14 TP15 TP18 TP19 TP20 TP21 TP22 TP23 TP24 TP25 TP26 TP27 TP28 TP29 TP30 TP31 TP32 TP33 TP34 TP35 TP36 TP37 TP38 TP39 TP40 TP41 TP42 TP43 TP44 TP45 TP46 TP47 TP49 TP50 TP51 TP52 TP53 TP54 TP55 TP56 TP57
